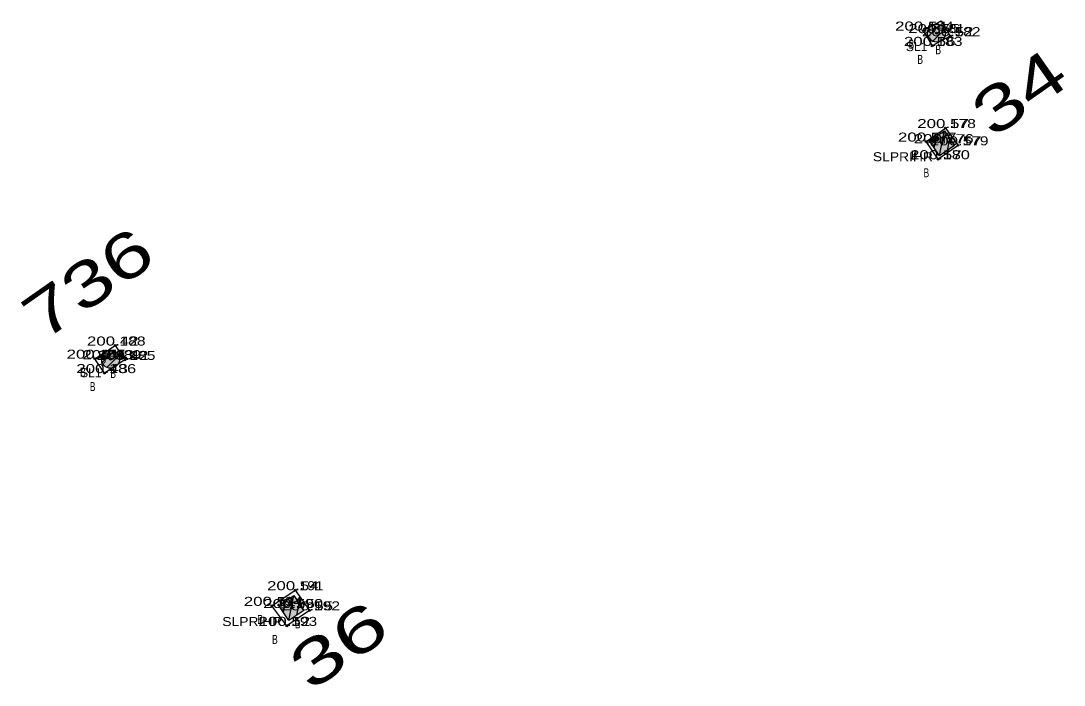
# Model space of a CAD drawing. Extents: x -466020 to -463400, y -1095586 to -1094005.
# Drawn here: x -463999.3 to -463941.4, y -1094461.6 to -1094424.7 of the extents above; entities that cross this region are included whole.
import ezdxf
from ezdxf.enums import TextEntityAlignment as Align

# ---------------------------------------------------------------- set-up
doc = ezdxf.new("R2010")
doc.units = 0
doc.header["$LTSCALE"] = 0.2
doc.header["$PDMODE"] = 32
doc.header["$PDSIZE"] = 0.1
for name, color, linetype in [('1', 7, 'Continuous'), ('2', 7, 'Continuous'), ('3', 7, 'Continuous'), ('4', 7, 'Continuous')]:
    doc.layers.add(name, color=color, linetype=linetype)
doc.layers.add('11', color=7, linetype='Continuous', lineweight=25)
doc.layers.add('12', color=7, linetype='Continuous', lineweight=25)

msp = doc.modelspace()

# ---------------------------------------------------------------- hatches: boundary and pattern name
at = {"layer": '11'}
for points in [[(-463948.03, -1094425.38, 1), (-463949.03, -1094425.38, 1)], [(-463948.914, -1094431.355), (-463948.085, -1094430.796), (-463947.526, -1094431.625), (-463948.355, -1094432.184)], [(-463993.84, -1094443.48, 1), (-463994.84, -1094443.48, 1)], [(-463985.002, -1094457.145), (-463984.165, -1094456.598), (-463983.618, -1094457.435), (-463984.455, -1094457.982)]]:
    msp.add_hatch(color=256, dxfattribs=at).paths.add_polyline_path(points)

# ---------------------------------------------------------------- linework, layer by layer
at = {"layer": '1'}
for p in [(-463949.26, -1094425.24), (-463948.53, -1094425.38), (-463947.77, -1094425.55), (-463948.77, -1094426.09), (-463948.03, -1094430.65), (-463949.1, -1094431.4), (-463948.22, -1094431.49), (-463947.33, -1094431.61), (-463948.43, -1094432.38), (-463994.09, -1094442.72), (-463995.22, -1094443.45), (-463994.34, -1094443.48), (-463993.54, -1094443.52), (-463994.68, -1094444.25), (-463984.1, -1094456.3), (-463985.39, -1094457.17), (-463984.31, -1094457.29), (-463983.3, -1094457.42), (-463984.57, -1094458.28)]:
    msp.add_point(p, dxfattribs=at)
at = {"layer": '11'}
for p, q in [((-463948.991, -1094425.564), (-463948.345, -1094424.918)), ((-463948.731, -1094425.834), (-463948.076, -1094425.179)), ((-463948.653, -1094431.742), (-463948.527, -1094431.095)), ((-463948.356, -1094432.182), (-463948.088, -1094430.798)), ((-463947.918, -1094431.889), (-463947.791, -1094431.233)), ((-463994.801, -1094443.664), (-463994.155, -1094443.018)), ((-463994.541, -1094443.934), (-463993.886, -1094443.279)), ((-463984.457, -1094457.979), (-463984.167, -1094456.6)), ((-463984.747, -1094457.536), (-463984.611, -1094456.889)), ((-463984.014, -1094457.694), (-463983.877, -1094457.039))]:
    msp.add_line(p, q, dxfattribs=at)
for points in [[(-463948.914, -1094431.355), (-463948.085, -1094430.796), (-463947.526, -1094431.625), (-463948.355, -1094432.184)], [(-463948.914, -1094431.355), (-463948.085, -1094430.796), (-463947.526, -1094431.625), (-463948.355, -1094432.184)], [(-463985.002, -1094457.145), (-463984.165, -1094456.598), (-463983.618, -1094457.435), (-463984.455, -1094457.982)], [(-463985.002, -1094457.145), (-463984.165, -1094456.598), (-463983.618, -1094457.435), (-463984.455, -1094457.982)]]:
    msp.add_lwpolyline(points, close=True, dxfattribs=at)
for centre in [(-463948.53, -1094425.38), (-463994.34, -1094443.48)]:
    msp.add_circle(centre, 0.5, dxfattribs=at)
at = {"layer": '12'}
for p, q in [((-463949.26, -1094425.24), (-463948.26, -1094424.7)), ((-463948.26, -1094424.7), (-463947.77, -1094425.55)), ((-463949.26, -1094425.24), (-463948.77, -1094426.09)), ((-463947.77, -1094425.55), (-463948.77, -1094426.09))]:
    msp.add_line(p, q, dxfattribs=at)
for points in [[(-463949.1, -1094431.4), (-463948.03, -1094430.65), (-463947.33, -1094431.61), (-463948.43, -1094432.38)], [(-463995.22, -1094443.45), (-463994.09, -1094442.72), (-463993.54, -1094443.52), (-463994.68, -1094444.25)], [(-463984.1, -1094456.3), (-463983.3, -1094457.42), (-463984.57, -1094458.28), (-463985.39, -1094457.17)]]:
    msp.add_lwpolyline(points, close=True, dxfattribs=at)

# ---------------------------------------------------------------- texts
at = {"layer": '11'}
for s, width, p in [('34', 1.45, (-463943.21, -1094429.7103)), ('736', 1.4, (-463994.881, -1094440.2799)), ('36', 1.5, (-463980.9695, -1094460.3648))]:
    msp.add_text(s, height=2.5, rotation=35, dxfattribs=dict(at, width=width)).set_placement(p, align=Align.CENTER)
at = {"layer": '2'}
for s, width, p in [(' 184', 1.3, (-463949.26, -1094425.24)), (' 181', 1.2, (-463948.53, -1094425.38)), (' 182', 1.3, (-463947.77, -1094425.55)), (' 183', 1.3, (-463948.77, -1094426.09)), (' 178', 1.3, (-463948.03, -1094430.65)), (' 177', 1.3, (-463949.1, -1094431.4)), (' 176', 1.35, (-463948.22, -1094431.49)), (' 179', 1.3, (-463947.33, -1094431.61)), (' 180', 1.35, (-463948.43, -1094432.38)), (' 188', 1.3, (-463994.09, -1094442.72)), (' 187', 1.3, (-463995.22, -1094443.45)), (' 189', 1.3, (-463994.34, -1094443.48)), (' 185', 1.3, (-463993.54, -1094443.52)), (' 186', 1.35, (-463994.68, -1094444.25)), (' 191', 1.2, (-463984.1, -1094456.3)), (' 194', 1.3, (-463985.39, -1094457.17)), (' 190', 1.35, (-463984.31, -1094457.29)), (' 192', 1.3, (-463983.3, -1094457.42)), (' 193', 1.3, (-463984.57, -1094458.28))]:
    msp.add_text(s, height=0.5, dxfattribs=dict(at, width=width)).set_placement(p)
at = {"layer": '3', "width": 1.4}
for s, p in [('200.54 ', (-463949.2595, -1094425.24)), ('200.55 ', (-463948.5295, -1094425.38)), ('200.52 ', (-463947.7695, -1094425.55)), ('200.56 ', (-463948.7695, -1094426.09)), ('200.57 ', (-463948.0295, -1094430.65)), ('200.57 ', (-463949.0995, -1094431.4)), ('200.57 ', (-463948.2195, -1094431.49)), ('200.57 ', (-463947.3295, -1094431.61)), ('200.57 ', (-463948.4295, -1094432.38)), ('200.42 ', (-463994.0895, -1094442.72)), ('200.44 ', (-463995.2195, -1094443.45)), ('200.43 ', (-463994.3395, -1094443.48)), ('200.42 ', (-463993.5395, -1094443.52)), ('200.43 ', (-463994.6795, -1094444.25)), ('200.54 ', (-463984.0995, -1094456.3)), ('200.51 ', (-463985.3895, -1094457.17)), ('200.55 ', (-463984.3095, -1094457.29)), ('200.55 ', (-463983.2995, -1094457.42)), ('200.52 ', (-463984.5695, -1094458.28))]:
    msp.add_text(s, height=0.5, dxfattribs=at).set_placement(p, align=Align.CENTER)
at = {"layer": '4'}
for p in [(-463949.03, -1094426.38), (-463994.84, -1094444.48)]:
    msp.add_text('SL1', height=0.5, dxfattribs=at).set_placement(p, align=Align.RIGHT)
for s, width, p in [('B', 0.7, (-463949.76, -1094426.24)), ('B', 0.7, (-463948.27, -1094426.55)), ('B', 0.7, (-463949.27, -1094427.09)), ('B', 0.7, (-463948.53, -1094431.65)), ('B', 0.7, (-463949.6, -1094432.4)), ('SLPRIHR', 1.15, (-463948.72, -1094432.49)), ('B', 0.7, (-463948.93, -1094433.38)), ('B', 0.7, (-463994.59, -1094443.72)), ('B', 0.7, (-463995.72, -1094444.45)), ('B', 0.7, (-463994.04, -1094444.52)), ('B', 0.7, (-463995.18, -1094445.25)), ('B', 0.7, (-463984.6, -1094457.3)), ('SLPRIHR', 1.15, (-463984.81, -1094458.29)), ('B', 0.7, (-463985.89, -1094458.17)), ('B', 0.7, (-463983.8, -1094458.42)), ('B', 0.7, (-463985.07, -1094459.28))]:
    msp.add_text(s, height=0.5, dxfattribs=dict(at, width=width)).set_placement(p, align=Align.RIGHT)

doc.saveas('drawing.dxf')
